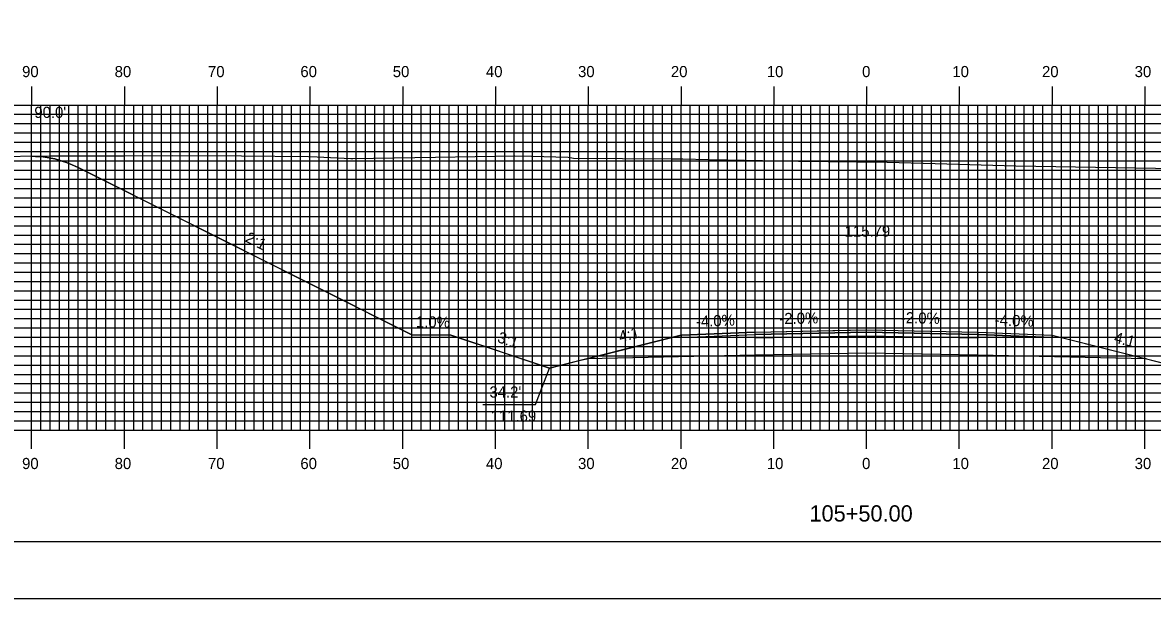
# Model space of a CAD drawing. Extents: x 1768087 to 1768430, y 442591 to 442811.
# Drawn here: x 1768162 to 1768283.8, y 442590.5 to 442652.5 of the extents above; entities that cross this region are included whole.
import ezdxf

# ---------------------------------------------------------------- set-up
doc = ezdxf.new("R2010")
doc.units = 0
for name, color, linetype in [('ANNOTATION', 7, 'Continuous'), ('BORDER', 7, 'Continuous'), ('D_Roadway_Centerline', 7, 'Continuous'), ('D_Roadway_Centerline_Text', 7, 'Continuous'), ('D_Roadway_Edge_Shoulder', 7, 'Continuous'), ('D_Roadway_Edge_TW', 7, 'Continuous'), ('D_Roadway_Pavement', 7, 'Continuous'), ('D_Roadway_SlopeLines', 7, 'Continuous'), ('D_Roadway_SubGrade', 7, 'Continuous'), ('D_Text_Standard', 7, 'Continuous'), ('H_V ANNOTATION', 7, 'Continuous'), ('MAJOR', 7, 'Continuous'), ('MINOR', 7, 'Continuous'), ('PLOT BOUNDARY', 7, 'Continuous'), ('S_Roadway_Centerline', 7, 'Continuous')]:
    doc.layers.add(name, color=color, linetype=linetype)

msp = doc.modelspace()

# ---------------------------------------------------------------- linework, layer by layer
at = {"layer": 'ANNOTATION'}
msp.add_lwpolyline([(1768211.58, 442611.44), (1768217.27, 442611.44), (1768218.79, 442615.35)], dxfattribs=at)
at = {"layer": 'BORDER'}
msp.add_lwpolyline([(1768103.36, 442596.67), (1768423.36, 442596.67), (1768423.36, 442806.67), (1768103.36, 442806.67)], close=True, dxfattribs=at)
at = {"layer": 'D_Roadway_Centerline'}
msp.add_lwpolyline([(1768162.96, 442638.16), (1768163.37, 442638.14), (1768164.21, 442638.09), (1768165.46, 442637.86), (1768166.71, 442637.48), (1768167.32, 442637.21), (1768167.96, 442636.93), (1768175.87, 442632.98), (1768203.95, 442618.94), (1768203.95, 442618.94), (1768208.16, 442618.9), (1768213.79, 442617.02), (1768218.79, 442615.35), (1768218.79, 442615.35), (1768222.13, 442616.19), (1768222.79, 442616.35), (1768232.96, 442618.9), (1768240.96, 442619.22), (1768240.96, 442619.22), (1768250.97, 442619.42), (1768252.96, 442619.46), (1768264.96, 442619.22), (1768264.96, 442619.22), (1768272.96, 442618.9), (1768272.97, 442618.9), (1768283.14, 442616.35), (1768287.13, 442615.35)], dxfattribs=at)
at = {"layer": 'D_Roadway_Edge_Shoulder'}
for points in [[(1768240.96, 442619.22), (1768232.96, 442618.9), (1768232.96, 442618.65), (1768240.96, 442618.97)], [(1768264.96, 442619.22), (1768272.96, 442618.9), (1768272.96, 442618.65), (1768264.96, 442618.97)]]:
    msp.add_lwpolyline(points, close=True, dxfattribs=at)
at = {"layer": 'D_Roadway_Edge_TW'}
msp.add_lwpolyline([(1768240.96, 442618.97), (1768240.96, 442619.22), (1768252.96, 442619.46), (1768264.96, 442619.22), (1768264.96, 442618.97), (1768252.96, 442619.21)], close=True, dxfattribs=at)
at = {"layer": 'D_Roadway_Pavement'}
msp.add_lwpolyline([(1768240.96, 442618.55), (1768240.96, 442618.97), (1768252.96, 442619.21), (1768264.96, 442618.97), (1768264.96, 442618.55), (1768252.96, 442618.79)], close=True, dxfattribs=at)
at = {"layer": 'D_Roadway_SlopeLines'}
for points in [[(1768208.16, 442618.9), (1768203.95, 442618.94), (1768167.96, 442636.93), (1768166.71, 442637.48), (1768165.46, 442637.86), (1768164.21, 442638.09), (1768162.96, 442638.16)], [(1768218.79, 442615.35), (1768208.16, 442618.9)], [(1768232.96, 442618.9), (1768218.79, 442615.35)], [(1768272.96, 442618.9), (1768287.14, 442615.35)]]:
    msp.add_lwpolyline(points, dxfattribs=at)
at = {"layer": 'D_Roadway_SubGrade'}
msp.add_lwpolyline([(1768240.96, 442616.72), (1768222.79, 442616.35), (1768232.96, 442618.9), (1768232.96, 442618.65), (1768240.96, 442618.97), (1768252.96, 442619.21), (1768264.96, 442618.97), (1768272.96, 442618.65), (1768272.96, 442618.9), (1768283.14, 442616.35), (1768264.96, 442616.72), (1768252.96, 442616.96)], close=True, dxfattribs=at)
at = {"layer": 'MAJOR'}
for p, q in [((1768162.96, 442645.67), (1768162.96, 442643.67)), ((1768172.96, 442645.67), (1768172.96, 442643.67)), ((1768182.96, 442645.67), (1768182.96, 442643.67)), ((1768192.96, 442645.67), (1768192.96, 442643.67)), ((1768202.96, 442645.67), (1768202.96, 442643.67)), ((1768212.96, 442645.67), (1768212.96, 442643.67)), ((1768222.96, 442645.67), (1768222.96, 442643.67)), ((1768232.96, 442645.67), (1768232.96, 442643.67)), ((1768242.96, 442645.67), (1768242.96, 442643.67)), ((1768252.96, 442645.67), (1768252.96, 442643.67)), ((1768262.96, 442645.67), (1768262.96, 442643.67)), ((1768272.96, 442645.67), (1768272.96, 442643.67)), ((1768282.96, 442645.67), (1768282.96, 442643.67)), ((1768112.96, 442643.67), (1768392.96, 442643.67)), ((1768112.96, 442643.67), (1768392.96, 442643.67)), ((1768162.96, 442608.67), (1768162.96, 442643.67)), ((1768172.96, 442608.67), (1768172.96, 442643.67)), ((1768182.96, 442608.67), (1768182.96, 442643.67)), ((1768192.96, 442608.67), (1768192.96, 442643.67)), ((1768202.96, 442608.67), (1768202.96, 442643.67)), ((1768212.96, 442608.67), (1768212.96, 442643.67)), ((1768222.96, 442608.67), (1768222.96, 442643.67)), ((1768232.96, 442608.67), (1768232.96, 442643.67)), ((1768242.96, 442608.67), (1768242.96, 442643.67)), ((1768252.96, 442608.67), (1768252.96, 442643.67)), ((1768262.96, 442608.67), (1768262.96, 442643.67)), ((1768272.96, 442608.67), (1768272.96, 442643.67)), ((1768282.96, 442608.67), (1768282.96, 442643.67)), ((1768112.96, 442638.67), (1768392.96, 442638.67)), ((1768112.96, 442633.67), (1768392.96, 442633.67)), ((1768112.96, 442628.67), (1768392.96, 442628.67)), ((1768112.96, 442623.67), (1768392.96, 442623.67)), ((1768112.96, 442618.67), (1768392.96, 442618.67)), ((1768112.96, 442613.67), (1768392.96, 442613.67)), ((1768112.96, 442608.67), (1768392.96, 442608.67)), ((1768112.96, 442608.67), (1768392.96, 442608.67)), ((1768162.96, 442606.66), (1768162.96, 442608.67)), ((1768172.96, 442606.66), (1768172.96, 442608.67)), ((1768182.96, 442606.66), (1768182.96, 442608.67)), ((1768192.96, 442606.66), (1768192.96, 442608.67)), ((1768202.96, 442606.66), (1768202.96, 442608.67)), ((1768212.96, 442606.66), (1768212.96, 442608.67)), ((1768222.96, 442606.66), (1768222.96, 442608.67)), ((1768232.96, 442606.66), (1768232.96, 442608.67)), ((1768242.96, 442606.66), (1768242.96, 442608.67)), ((1768252.96, 442606.66), (1768252.96, 442608.67)), ((1768262.96, 442606.66), (1768262.96, 442608.67)), ((1768272.96, 442606.66), (1768272.96, 442608.67)), ((1768282.96, 442606.66), (1768282.96, 442608.67))]:
    msp.add_line(p, q, dxfattribs=at)
at = {"layer": 'MINOR'}
for p, q in [((1768163.96, 442608.67), (1768163.96, 442643.67)), ((1768164.96, 442608.67), (1768164.96, 442643.67)), ((1768165.96, 442608.67), (1768165.96, 442643.67)), ((1768166.96, 442608.67), (1768166.96, 442643.67)), ((1768167.96, 442608.67), (1768167.96, 442643.67)), ((1768168.96, 442608.67), (1768168.96, 442643.67)), ((1768169.96, 442608.67), (1768169.96, 442643.67)), ((1768170.96, 442608.67), (1768170.96, 442643.67)), ((1768171.96, 442608.67), (1768171.96, 442643.67)), ((1768173.96, 442608.67), (1768173.96, 442643.67)), ((1768174.96, 442608.67), (1768174.96, 442643.67)), ((1768175.96, 442608.67), (1768175.96, 442643.67)), ((1768176.96, 442608.67), (1768176.96, 442643.67)), ((1768177.96, 442608.67), (1768177.96, 442643.67)), ((1768178.96, 442608.67), (1768178.96, 442643.67)), ((1768179.96, 442608.67), (1768179.96, 442643.67)), ((1768180.96, 442608.67), (1768180.96, 442643.67)), ((1768181.96, 442608.67), (1768181.96, 442643.67)), ((1768183.96, 442608.67), (1768183.96, 442643.67)), ((1768184.96, 442608.67), (1768184.96, 442643.67)), ((1768185.96, 442608.67), (1768185.96, 442643.67)), ((1768186.96, 442608.67), (1768186.96, 442643.67)), ((1768187.96, 442608.67), (1768187.96, 442643.67)), ((1768188.96, 442608.67), (1768188.96, 442643.67)), ((1768189.96, 442608.67), (1768189.96, 442643.67)), ((1768190.96, 442608.67), (1768190.96, 442643.67)), ((1768191.96, 442608.67), (1768191.96, 442643.67)), ((1768193.96, 442608.67), (1768193.96, 442643.67)), ((1768194.96, 442608.67), (1768194.96, 442643.67)), ((1768195.96, 442608.67), (1768195.96, 442643.67)), ((1768196.96, 442608.67), (1768196.96, 442643.67)), ((1768197.96, 442608.67), (1768197.96, 442643.67)), ((1768198.96, 442608.67), (1768198.96, 442643.67)), ((1768199.96, 442608.67), (1768199.96, 442643.67)), ((1768200.96, 442608.67), (1768200.96, 442643.67)), ((1768201.96, 442608.67), (1768201.96, 442643.67)), ((1768203.96, 442608.67), (1768203.96, 442643.67)), ((1768204.96, 442608.67), (1768204.96, 442643.67)), ((1768205.96, 442608.67), (1768205.96, 442643.67)), ((1768206.96, 442608.67), (1768206.96, 442643.67)), ((1768207.96, 442608.67), (1768207.96, 442643.67)), ((1768208.96, 442608.67), (1768208.96, 442643.67)), ((1768209.96, 442608.67), (1768209.96, 442643.67)), ((1768210.96, 442608.67), (1768210.96, 442643.67)), ((1768211.96, 442608.67), (1768211.96, 442643.67)), ((1768213.96, 442608.67), (1768213.96, 442643.67)), ((1768214.96, 442608.67), (1768214.96, 442643.67)), ((1768215.96, 442608.67), (1768215.96, 442643.67)), ((1768216.96, 442608.67), (1768216.96, 442643.67)), ((1768217.96, 442608.67), (1768217.96, 442643.67)), ((1768218.96, 442608.67), (1768218.96, 442643.67)), ((1768219.96, 442608.67), (1768219.96, 442643.67)), ((1768220.96, 442608.67), (1768220.96, 442643.67)), ((1768221.96, 442608.67), (1768221.96, 442643.67)), ((1768223.96, 442608.67), (1768223.96, 442643.67)), ((1768224.96, 442608.67), (1768224.96, 442643.67)), ((1768225.96, 442608.67), (1768225.96, 442643.67)), ((1768226.96, 442608.67), (1768226.96, 442643.67)), ((1768227.96, 442608.67), (1768227.96, 442643.67)), ((1768228.96, 442608.67), (1768228.96, 442643.67)), ((1768229.96, 442608.67), (1768229.96, 442643.67)), ((1768230.96, 442608.67), (1768230.96, 442643.67)), ((1768231.96, 442608.67), (1768231.96, 442643.67)), ((1768233.96, 442608.67), (1768233.96, 442643.67)), ((1768234.96, 442608.67), (1768234.96, 442643.67)), ((1768235.96, 442608.67), (1768235.96, 442643.67)), ((1768236.96, 442608.67), (1768236.96, 442643.67)), ((1768237.96, 442608.67), (1768237.96, 442643.67)), ((1768238.96, 442608.67), (1768238.96, 442643.67)), ((1768239.96, 442608.67), (1768239.96, 442643.67)), ((1768240.96, 442608.67), (1768240.96, 442643.67)), ((1768241.96, 442608.67), (1768241.96, 442643.67)), ((1768243.96, 442608.67), (1768243.96, 442643.67)), ((1768244.96, 442608.67), (1768244.96, 442643.67)), ((1768245.96, 442608.67), (1768245.96, 442643.67)), ((1768246.96, 442608.67), (1768246.96, 442643.67)), ((1768247.96, 442608.67), (1768247.96, 442643.67)), ((1768248.96, 442608.67), (1768248.96, 442643.67)), ((1768249.96, 442608.67), (1768249.96, 442643.67)), ((1768250.96, 442608.67), (1768250.96, 442643.67)), ((1768251.96, 442608.67), (1768251.96, 442643.67)), ((1768253.96, 442608.67), (1768253.96, 442643.67)), ((1768254.96, 442608.67), (1768254.96, 442643.67)), ((1768255.96, 442608.67), (1768255.96, 442643.67)), ((1768256.96, 442608.67), (1768256.96, 442643.67)), ((1768257.96, 442608.67), (1768257.96, 442643.67)), ((1768258.96, 442608.67), (1768258.96, 442643.67)), ((1768259.96, 442608.67), (1768259.96, 442643.67)), ((1768260.96, 442608.67), (1768260.96, 442643.67)), ((1768261.96, 442608.67), (1768261.96, 442643.67)), ((1768263.96, 442608.67), (1768263.96, 442643.67)), ((1768264.96, 442608.67), (1768264.96, 442643.67)), ((1768265.96, 442608.67), (1768265.96, 442643.67)), ((1768266.96, 442608.67), (1768266.96, 442643.67)), ((1768267.96, 442608.67), (1768267.96, 442643.67)), ((1768268.96, 442608.67), (1768268.96, 442643.67)), ((1768269.96, 442608.67), (1768269.96, 442643.67)), ((1768270.96, 442608.67), (1768270.96, 442643.67)), ((1768271.96, 442608.67), (1768271.96, 442643.67)), ((1768273.96, 442608.67), (1768273.96, 442643.67)), ((1768274.96, 442608.67), (1768274.96, 442643.67)), ((1768275.96, 442608.67), (1768275.96, 442643.67)), ((1768276.96, 442608.67), (1768276.96, 442643.67)), ((1768277.96, 442608.67), (1768277.96, 442643.67)), ((1768278.96, 442608.67), (1768278.96, 442643.67)), ((1768279.96, 442608.67), (1768279.96, 442643.67)), ((1768280.96, 442608.67), (1768280.96, 442643.67)), ((1768281.96, 442608.67), (1768281.96, 442643.67)), ((1768112.96, 442642.67), (1768392.96, 442642.67)), ((1768112.96, 442641.67), (1768392.96, 442641.67)), ((1768112.96, 442640.67), (1768392.96, 442640.67)), ((1768112.96, 442639.67), (1768392.96, 442639.67)), ((1768112.96, 442637.67), (1768392.96, 442637.67)), ((1768112.96, 442636.67), (1768392.96, 442636.67)), ((1768112.96, 442635.67), (1768392.96, 442635.67)), ((1768112.96, 442634.67), (1768392.96, 442634.67)), ((1768112.96, 442632.67), (1768392.96, 442632.67)), ((1768112.96, 442631.67), (1768392.96, 442631.67)), ((1768112.96, 442630.67), (1768392.96, 442630.67)), ((1768112.96, 442629.67), (1768392.96, 442629.67)), ((1768112.96, 442627.67), (1768392.96, 442627.67)), ((1768112.96, 442626.67), (1768392.96, 442626.67)), ((1768112.96, 442625.67), (1768392.96, 442625.67)), ((1768112.96, 442624.67), (1768392.96, 442624.67)), ((1768112.96, 442622.67), (1768392.96, 442622.67)), ((1768112.96, 442621.67), (1768392.96, 442621.67)), ((1768112.96, 442620.67), (1768392.96, 442620.67)), ((1768112.96, 442619.67), (1768392.96, 442619.67)), ((1768112.96, 442617.67), (1768392.96, 442617.67)), ((1768112.96, 442616.67), (1768392.96, 442616.67)), ((1768112.96, 442615.67), (1768392.96, 442615.67)), ((1768112.96, 442614.67), (1768392.96, 442614.67)), ((1768112.96, 442612.67), (1768392.96, 442612.67)), ((1768112.96, 442611.67), (1768392.96, 442611.67)), ((1768112.96, 442610.67), (1768392.96, 442610.67)), ((1768112.96, 442609.67), (1768392.96, 442609.67))]:
    msp.add_line(p, q, dxfattribs=at)
at = {"layer": 'PLOT BOUNDARY'}
msp.add_lwpolyline([(1768087.18, 442590.55), (1768427.18, 442590.55), (1768427.18, 442810.55), (1768087.18, 442810.55)], close=True, dxfattribs=at)
at = {"layer": 'S_Roadway_Centerline'}
msp.add_lwpolyline([(1768158.42, 442638.11), (1768165.04, 442638.18), (1768172.99, 442638.19), (1768178.11, 442638.22), (1768185.59, 442638.19), (1768192.8, 442638.11), (1768193.75, 442638.09), (1768197.37, 442637.91), (1768197.59, 442637.91), (1768206.51, 442638.05), (1768215.03, 442638.2), (1768216.83, 442638.17), (1768220.78, 442638.05), (1768221.38, 442637.94), (1768231.95, 442637.87), (1768233.17, 442637.86), (1768235.91, 442637.79), (1768245.61, 442637.63), (1768255.18, 442637.5), (1768260.36, 442637.36), (1768269.05, 442637.11), (1768292.69, 442636.71)], dxfattribs=at)

# ---------------------------------------------------------------- texts
at = {"layer": 'ANNOTATION'}
for s, rotation, p in [('2:1', 333.4354, (1768185.89, 442629)), ('1.0%', 359.428, (1768204.38, 442619.73)), ('-4.0%', 2.2905, (1768234.59, 442619.76)), ('-2.0%', 1.1458, (1768243.57, 442620.07)), ('-2.0%', 358.8542, (1768256.65, 442620.18)), ('-4.0%', 357.7095, (1768266.76, 442619.95)), ('3:1', 341.563, (1768213.08, 442618.16)), ('4:1', 14.0395, (1768226.41, 442618.12)), ('4:1', 345.9611, (1768279.56, 442618.11))]:
    msp.add_text(s, height=1.2, rotation=rotation, dxfattribs=at).set_placement(p)
for s, p in [("34.2'", (1768212.31, 442612.17)), ('111.69', (1768212.44, 442609.57))]:
    msp.add_text(s, height=1.2, dxfattribs=at).set_placement(p)
at = {"layer": 'D_Roadway_Centerline'}
for s, p in [('C', (1768252.96, 442619.46)), ('L', (1768252.96, 442619.45))]:
    msp.add_text(s, height=0.0146, dxfattribs=at).set_placement(p)
at = {"layer": 'D_Roadway_Centerline_Text'}
msp.add_text('115.79', height=1.2, dxfattribs=at).set_placement((1768250.6, 442629.49))
at = {"layer": 'D_Text_Standard'}
msp.add_text("90.0'", height=1.2, dxfattribs=at).set_placement((1768163.25, 442642.28))
at = {"layer": 'H_V ANNOTATION'}
for s, height, p in [('90', 1.2, (1768161.93, 442646.67)), ('80', 1.2, (1768171.91, 442646.67)), ('70', 1.2, (1768181.97, 442646.67)), ('60', 1.2, (1768191.93, 442646.67)), ('50', 1.2, (1768201.89, 442646.67)), ('40', 1.2, (1768211.93, 442646.67)), ('30', 1.2, (1768221.86, 442646.67)), ('20', 1.2, (1768231.87, 442646.67)), ('10', 1.2, (1768242.21, 442646.67)), ('0', 1.2, (1768252.48, 442646.67)), ('10', 1.2, (1768262.21, 442646.67)), ('20', 1.2, (1768271.87, 442646.67)), ('30', 1.2, (1768281.86, 442646.67)), ('90', 1.2, (1768161.93, 442604.47)), ('80', 1.2, (1768171.91, 442604.47)), ('70', 1.2, (1768181.97, 442604.47)), ('60', 1.2, (1768191.93, 442604.47)), ('50', 1.2, (1768201.89, 442604.47)), ('40', 1.2, (1768211.93, 442604.47)), ('30', 1.2, (1768221.86, 442604.47)), ('20', 1.2, (1768231.87, 442604.47)), ('10', 1.2, (1768242.21, 442604.47)), ('0', 1.2, (1768252.48, 442604.47)), ('10', 1.2, (1768262.21, 442604.47)), ('20', 1.2, (1768271.87, 442604.47)), ('30', 1.2, (1768281.86, 442604.47)), ('105+50.00', 1.75, (1768246.81, 442598.82))]:
    msp.add_text(s, height=height, dxfattribs=at).set_placement(p)

doc.saveas('drawing.dxf')
